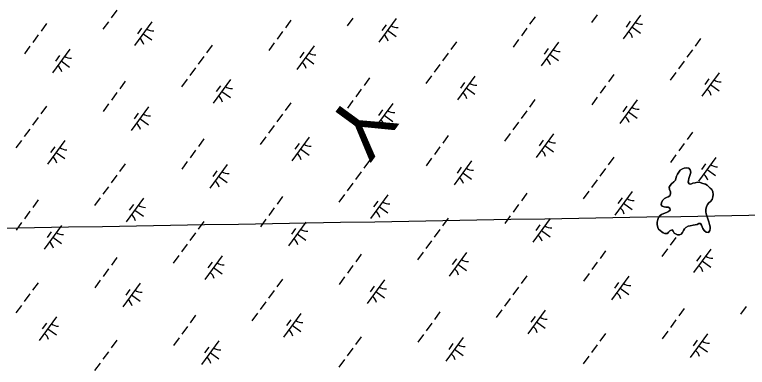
# Model space of a CAD drawing. Extents: x 3905714 to 3926767, y 183354 to 205755.
# Drawn here: x 3912599 to 3913848, y 193112 to 193713 of the extents above; entities that cross this region are included whole.
import ezdxf

# ---------------------------------------------------------------- set-up
doc = ezdxf.new("R2010")
doc.units = 0
for name, color, linetype in [('V-GRID-MAJR', 7, 'Continuous'), ('V-RIVR-IDEN', 7, 'Continuous'), ('V-TOPO-SHOR', 7, 'Continuous'), ('V-WETL-SWMP', 7, 'Continuous')]:
    doc.layers.add(name, color=color, linetype=linetype)

msp = doc.modelspace()

# ---------------------------------------------------------------- linework, layer by layer
at = {"layer": 'V-GRID-MAJR'}
msp.add_spline([(3911066.2, 193323.4), (3914779.2, 193387.5), (3920106, 193480.1), (3922587.2, 193523.5)], degree=3, dxfattribs=at)
at = {"layer": 'V-TOPO-SHOR'}
for points in [[(3913755.8, 193354.6), (3913751.1, 193353.4), (3913747.3, 193352.5), (3913743.7, 193350.7), (3913741.4, 193348.3), (3913739.7, 193345.3), (3913738, 193342), (3913735.7, 193339.4), (3913732.8, 193338), (3913729.5, 193338), (3913726, 193339.5), (3913723.4, 193341.1), (3913721.8, 193344), (3913719.9, 193346.3), (3913715.9, 193344.9), (3913714, 193342.3), (3913711.9, 193340), (3913707.9, 193340), (3913704.8, 193341.2), (3913702.3, 193342.9), (3913699.4, 193345.3), (3913697.1, 193347.6), (3913695.9, 193350.7), (3913694.8, 193355.6), (3913694.6, 193359.4), (3913695.6, 193364.1), (3913697, 193367.6), (3913699.4, 193370.7), (3913701.7, 193372.6), (3913705.7, 193374.4), (3913710.5, 193376), (3913714, 193377.7), (3913716.6, 193379.8), (3913716.2, 193383.5), (3913713.3, 193385.2), (3913709.6, 193385), (3913706.3, 193385.5), (3913703, 193386.7), (3913701.4, 193389.3), (3913701.8, 193393), (3913704.2, 193397.3), (3913707.1, 193399.8), (3913710.6, 193401.5), (3913713.4, 193402.6), (3913716, 193404.7), (3913717.5, 193407.8), (3913717.5, 193411.3), (3913715.6, 193415.1), (3913715.2, 193419.1), (3913716.6, 193422.2), (3913719.2, 193425), (3913723, 193428.2), (3913725.9, 193431.1), (3913726.6, 193434.1), (3913727.3, 193438.3), (3913729.2, 193441.6), (3913731.3, 193444.9), (3913733.5, 193448.2), (3913737.5, 193450.5), (3913740.8, 193451.7), (3913744.8, 193452.1), (3913748.3, 193451.9), (3913750.9, 193449), (3913751.8, 193444.6), (3913751.1, 193440.6), (3913749.7, 193437.3), (3913748.7, 193434), (3913747.8, 193430.9), (3913747.3, 193427.6), (3913749.1, 193424.8), (3913752.2, 193424.5), (3913755.5, 193425.9), (3913759.5, 193426.9), (3913763.5, 193427.8), (3913768, 193427), (3913772.2, 193425.8), (3913777.1, 193424.2), (3913780, 193422.5), (3913782.3, 193420.4), (3913784.9, 193417.8), (3913787.5, 193415.4), (3913789.6, 193411.4), (3913790.2, 193406.9), (3913789.5, 193402.7), (3913788.3, 193398.2), (3913785.5, 193394.9), (3913782.8, 193392.6), (3913780.2, 193389.8), (3913778.6, 193385.8), (3913777.4, 193382), (3913777.6, 193377.3), (3913778, 193374), (3913779.9, 193368.8), (3913780.8, 193365.3), (3913782.4, 193360.1), (3913783.8, 193355.6), (3913784.7, 193351.6), (3913784.7, 193348.5), (3913784.5, 193345.5), (3913782.3, 193342.2), (3913778.1, 193342.4)], [(3913778.1, 193342.4), (3913774.6, 193345.5), (3913772.5, 193348.8), (3913770.1, 193354.5), (3913768.7, 193357.3), (3913765.7, 193357.1), (3913762.6, 193355.7), (3913755.8, 193354.6)]]:
    msp.add_lwpolyline(points, dxfattribs=at)
at = {"layer": 'V-WETL-SWMP'}
for p, q in [((3912772.8, 193720.9), (3912763.4, 193708)), ((3913175.3, 193707.3), (3913165.9, 193694.4)), ((3913249.5, 193707), (3913220, 193666.7)), ((3913486.6, 193709.9), (3913477.1, 193697)), ((3913592, 193713.2), (3913582.6, 193700.3)), ((3913666.2, 193712.8), (3913636.6, 193672.5)), ((3912653.2, 193698.2), (3912643.8, 193685.3)), ((3912758.7, 193701.5), (3912749.2, 193688.6)), ((3912832.8, 193701.2), (3912803.3, 193660.9)), ((3913069.9, 193704), (3913060.5, 193691.1)), ((3913232.1, 193696.2), (3913225, 193686.6)), ((3913648.7, 193702.1), (3913641.6, 193692.4)), ((3913651.4, 193692.7), (3913665.9, 193682)), ((3912815.4, 193690.4), (3912808.3, 193680.7)), ((3912818.1, 193681), (3912832.6, 193670.4)), ((3913055.7, 193684.7), (3913046.3, 193671.8)), ((3913234.7, 193686.8), (3913249.3, 193676.2)), ((3913472.4, 193690.5), (3913463, 193677.6)), ((3912639.1, 193678.9), (3912629.6, 193666)), ((3913352.1, 193667.1), (3913342.6, 193654.2)), ((3913458.2, 193671.2), (3913448.8, 193658.2)), ((3913768.7, 193672.9), (3913759.3, 193660)), ((3912624.9, 193659.5), (3912615.4, 193646.6)), ((3912692.9, 193654.7), (3912663.3, 193614.3)), ((3912935.4, 193661.3), (3912925.9, 193648.4)), ((3913041.6, 193665.3), (3913032.1, 193652.4)), ((3913109.6, 193660.5), (3913080, 193620.2)), ((3913526.2, 193666.3), (3913496.7, 193626)), ((3913508.8, 193655.6), (3913501.7, 193645.9)), ((3912675.4, 193643.9), (3912668.3, 193634.2)), ((3913092.1, 193649.7), (3913085, 193640)), ((3913337.9, 193647.8), (3913328.4, 193634.8)), ((3913511.5, 193646.2), (3913526, 193635.5)), ((3913754.6, 193653.6), (3913745.1, 193640.7)), ((3912678.1, 193634.5), (3912692.6, 193623.9)), ((3912921.2, 193641.9), (3912911.8, 193629)), ((3913094.8, 193640.3), (3913109.3, 193629.7)), ((3913740.4, 193634.2), (3913730.9, 193621.3)), ((3912907, 193622.6), (3912897.6, 193609.7)), ((3913323.7, 193628.4), (3913314.2, 193615.5)), ((3913204.1, 193605.7), (3913194.6, 193592.8)), ((3913309.5, 193609), (3913300.1, 193596.1)), ((3913383.7, 193608.7), (3913354.1, 193568.4)), ((3913620.8, 193611.6), (3913611.3, 193598.7)), ((3913726.2, 193614.9), (3913716.7, 193601.9)), ((3913800.4, 193614.5), (3913770.8, 193574.2)), ((3912787.4, 193599.9), (3912778, 193587)), ((3912892.8, 193603.2), (3912883.4, 193590.3)), ((3912967, 193602.9), (3912937.5, 193562.5)), ((3912949.6, 193592.1), (3912942.5, 193582.4)), ((3913366.2, 193597.9), (3913359.2, 193588.3)), ((3913606.6, 193592.2), (3913597.1, 193579.3)), ((3913782.9, 193603.8), (3913775.8, 193594.1)), ((3913785.6, 193594.4), (3913800.1, 193583.7)), ((3912773.2, 193580.6), (3912763.8, 193567.6)), ((3912952.2, 193582.7), (3912966.8, 193572.1)), ((3913189.9, 193586.4), (3913180.5, 193573.5)), ((3913368.9, 193588.5), (3913383.4, 193577.9)), ((3913175.7, 193567), (3913166.3, 193554.1)), ((3913486.2, 193568.8), (3913476.8, 193555.9)), ((3913592.4, 193572.8), (3913583, 193559.9)), ((3913660.4, 193568), (3913630.9, 193527.7)), ((3912652.9, 193557.2), (3912643.4, 193544.2)), ((3912759.1, 193561.2), (3912749.6, 193548.3)), ((3912827.1, 193556.4), (3912797.5, 193516)), ((3913069.6, 193563), (3913060.1, 193550.1)), ((3913243.7, 193562.2), (3913214.2, 193521.9)), ((3913643, 193557.2), (3913635.9, 193547.6)), ((3912809.6, 193545.6), (3912802.5, 193535.9)), ((3913055.4, 193543.6), (3913045.9, 193530.7)), ((3913226.3, 193551.4), (3913219.2, 193541.7)), ((3913229, 193542), (3913243.5, 193531.4)), ((3913472.1, 193549.4), (3913462.6, 193536.5)), ((3913645.6, 193547.8), (3913660.2, 193537.2)), ((3912638.7, 193537.8), (3912629.3, 193524.9)), ((3912812.3, 193536.2), (3912826.8, 193525.6)), ((3913457.9, 193530.1), (3913448.4, 193517.2)), ((3912624.5, 193518.4), (3912615.1, 193505.5)), ((3913041.2, 193524.3), (3913031.7, 193511.4)), ((3913027, 193504.9), (3913017.6, 193492)), ((3913101.2, 193504.6), (3913071.7, 193464.2)), ((3913338.3, 193507.4), (3913328.8, 193494.5)), ((3913443.7, 193510.7), (3913434.2, 193497.8)), ((3913517.9, 193510.4), (3913488.3, 193470.1)), ((3913755, 193513.3), (3913745.5, 193500.4)), ((3912610.3, 193499.1), (3912600.9, 193486.2)), ((3912684.5, 193498.7), (3912655, 193458.4)), ((3912921.6, 193501.6), (3912912.2, 193488.7)), ((3913083.8, 193493.8), (3913076.7, 193484.1)), ((3913500.4, 193499.6), (3913493.3, 193490)), ((3913740.8, 193493.9), (3913731.3, 193481)), ((3912667.1, 193488), (3912660, 193478.3)), ((3912907.4, 193482.2), (3912898, 193469.3)), ((3913086.4, 193484.4), (3913100.9, 193473.8)), ((3913324.1, 193488.1), (3913314.6, 193475.2)), ((3913503.1, 193490.2), (3913517.6, 193479.6)), ((3912669.8, 193478.6), (3912684.3, 193467.9)), ((3913309.9, 193468.7), (3913300.5, 193455.8)), ((3913620.4, 193470.5), (3913611, 193457.6)), ((3913726.6, 193474.5), (3913717.1, 193461.6)), ((3913794.6, 193469.7), (3913765, 193429.4)), ((3912787.1, 193458.8), (3912777.6, 193445.9)), ((3912893.2, 193462.9), (3912883.8, 193450)), ((3912961.2, 193458.1), (3912931.7, 193417.7)), ((3913203.8, 193464.7), (3913194.3, 193451.8)), ((3913377.9, 193463.9), (3913348.4, 193423.5)), ((3913777.1, 193458.9), (3913770, 193449.3)), ((3912943.8, 193447.3), (3912936.7, 193437.6)), ((3913189.6, 193445.3), (3913180.1, 193432.4)), ((3913360.5, 193453.1), (3913353.4, 193443.4)), ((3913363.1, 193443.7), (3913377.7, 193433.1)), ((3913606.2, 193451.1), (3913596.8, 193438.2)), ((3913731.3, 193444.9), (3913729.2, 193441.6)), ((3913733.5, 193448.2), (3913731.3, 193444.9)), ((3913737.5, 193450.5), (3913733.5, 193448.2)), ((3913740.8, 193451.7), (3913737.5, 193450.5)), ((3913744.8, 193452.1), (3913740.8, 193451.7)), ((3913748.3, 193451.9), (3913744.8, 193452.1)), ((3913750.9, 193449), (3913748.3, 193451.9)), ((3913751.8, 193444.6), (3913750.9, 193449)), ((3913751.1, 193440.6), (3913751.8, 193444.6)), ((3913779.8, 193449.5), (3913794.3, 193438.9)), ((3912772.9, 193439.5), (3912763.4, 193426.6)), ((3912946.5, 193437.9), (3912961, 193427.3)), ((3913592.1, 193431.8), (3913582.6, 193418.9)), ((3913725.9, 193431.1), (3913723, 193428.2)), ((3913726.6, 193434.1), (3913725.9, 193431.1)), ((3913727.3, 193438.3), (3913726.6, 193434.1)), ((3913729.2, 193441.6), (3913727.3, 193438.3)), ((3913747.3, 193427.6), (3913747.8, 193430.9)), ((3913747.8, 193430.9), (3913748.7, 193434)), ((3913748.7, 193434), (3913749.7, 193437.3)), ((3913749.7, 193437.3), (3913751.1, 193440.6)), ((3912758.7, 193420.1), (3912749.3, 193407.2)), ((3913175.4, 193426), (3913165.9, 193413)), ((3913716.6, 193422.2), (3913715.2, 193419.1)), ((3913715.2, 193419.1), (3913715.6, 193415.1)), ((3913719.2, 193425), (3913716.6, 193422.2)), ((3913723, 193428.2), (3913719.2, 193425)), ((3913749.1, 193424.8), (3913747.3, 193427.6)), ((3913752.2, 193424.5), (3913749.1, 193424.8)), ((3913755.5, 193425.9), (3913752.2, 193424.5)), ((3913759.5, 193426.9), (3913755.5, 193425.9)), ((3913763.5, 193427.8), (3913759.5, 193426.9)), ((3913768, 193427), (3913763.5, 193427.8)), ((3913772.2, 193425.8), (3913768, 193427)), ((3913777.1, 193424.2), (3913772.2, 193425.8)), ((3913780, 193422.5), (3913777.1, 193424.2)), ((3913782.3, 193420.4), (3913780, 193422.5)), ((3913784.9, 193417.8), (3913782.3, 193420.4)), ((3913787.5, 193415.4), (3913784.9, 193417.8)), ((3913161.2, 193406.6), (3913151.7, 193393.7)), ((3913235.4, 193406.3), (3913205.8, 193365.9)), ((3913472.5, 193409.1), (3913463, 193396.2)), ((3913577.9, 193412.4), (3913568.4, 193399.5)), ((3913652.1, 193412.1), (3913622.5, 193371.8)), ((3913716, 193404.7), (3913713.4, 193402.6)), ((3913715.6, 193415.1), (3913717.5, 193411.3)), ((3913717.5, 193407.8), (3913716, 193404.7)), ((3913717.5, 193411.3), (3913717.5, 193407.8)), ((3913789.6, 193411.4), (3913787.5, 193415.4)), ((3913789.5, 193402.7), (3913790.2, 193406.9)), ((3913790.2, 193406.9), (3913789.6, 193411.4)), ((3912639.1, 193397.5), (3912629.7, 193384.6)), ((3912744.5, 193400.8), (3912735.1, 193387.9)), ((3912818.7, 193400.4), (3912789.2, 193360.1)), ((3913055.8, 193403.3), (3913046.3, 193390.4)), ((3913217.9, 193395.5), (3913210.8, 193385.8)), ((3913634.6, 193401.3), (3913627.5, 193391.6)), ((3913701.8, 193393), (3913701.4, 193389.3)), ((3913704.2, 193397.3), (3913701.8, 193393)), ((3913707.1, 193399.8), (3913704.2, 193397.3)), ((3913710.6, 193401.5), (3913707.1, 193399.8)), ((3913713.4, 193402.6), (3913710.6, 193401.5)), ((3913780.2, 193389.8), (3913782.8, 193392.6)), ((3913782.8, 193392.6), (3913785.5, 193394.9)), ((3913785.5, 193394.9), (3913788.3, 193398.2)), ((3913788.3, 193398.2), (3913789.5, 193402.7)), ((3912801.3, 193389.7), (3912794.2, 193380)), ((3912803.9, 193380.3), (3912818.5, 193369.6)), ((3913041.6, 193383.9), (3913032.1, 193371)), ((3913220.6, 193386.1), (3913235.1, 193375.5)), ((3913458.3, 193389.8), (3913448.8, 193376.9)), ((3913637.3, 193391.9), (3913651.8, 193381.3)), ((3913701.4, 193389.3), (3913703, 193386.7)), ((3913703, 193386.7), (3913706.3, 193385.5)), ((3913706.3, 193385.5), (3913709.6, 193385)), ((3913709.6, 193385), (3913713.3, 193385.2)), ((3913713.3, 193385.2), (3913716.2, 193383.5)), ((3913716.6, 193379.8), (3913714, 193377.7)), ((3913716.2, 193383.5), (3913716.6, 193379.8)), ((3913777.4, 193382), (3913778.6, 193385.8)), ((3913777.6, 193377.3), (3913777.4, 193382)), ((3913778.6, 193385.8), (3913780.2, 193389.8)), ((3912624.9, 193378.1), (3912615.5, 193365.2)), ((3913444.1, 193370.4), (3913434.6, 193357.5)), ((3913697, 193367.6), (3913695.6, 193364.1)), ((3913699.4, 193370.7), (3913697, 193367.6)), ((3913701.7, 193372.6), (3913699.4, 193370.7)), ((3913705.7, 193374.4), (3913701.7, 193372.6)), ((3913710.5, 193376), (3913705.7, 193374.4)), ((3913714, 193377.7), (3913710.5, 193376)), ((3913778, 193374), (3913777.6, 193377.3)), ((3913779.9, 193368.8), (3913778, 193374)), ((3913780.8, 193365.3), (3913779.9, 193368.8)), ((3912610.7, 193358.8), (3912601.3, 193345.9)), ((3912921.3, 193360.5), (3912911.8, 193347.6)), ((3913027.4, 193364.6), (3913018, 193351.7)), ((3913095.4, 193359.8), (3913065.9, 193319.4)), ((3913337.9, 193366.4), (3913328.5, 193353.5)), ((3913512.1, 193365.6), (3913482.6, 193325.2)), ((3913494.6, 193354.8), (3913487.6, 193345.1)), ((3913695.6, 193364.1), (3913694.6, 193359.4)), ((3913694.6, 193359.4), (3913694.8, 193355.6)), ((3913694.8, 193355.6), (3913695.9, 193350.7)), ((3913751.1, 193353.4), (3913755.8, 193354.6)), ((3913755.8, 193354.6), (3913762.6, 193355.7)), ((3913762.6, 193355.7), (3913765.7, 193357.1)), ((3913765.7, 193357.1), (3913768.7, 193357.3)), ((3913768.7, 193357.3), (3913770.1, 193354.5)), ((3913782.4, 193360.1), (3913780.8, 193365.3)), ((3913783.8, 193355.6), (3913782.4, 193360.1)), ((3913784.7, 193351.6), (3913783.8, 193355.6)), ((3912678.8, 193353.9), (3912649.2, 193313.6)), ((3912661.3, 193343.2), (3912654.2, 193333.5)), ((3913078, 193349), (3913070.9, 193339.3)), ((3913323.7, 193347), (3913314.3, 193334.1)), ((3913497.3, 193345.4), (3913511.8, 193334.8)), ((3913695.9, 193350.7), (3913697.1, 193347.6)), ((3913697.1, 193347.6), (3913699.4, 193345.3)), ((3913699.4, 193345.3), (3913702.3, 193342.9)), ((3913702.3, 193342.9), (3913704.8, 193341.2)), ((3913711.9, 193340), (3913714, 193342.3)), ((3913714, 193342.3), (3913715.9, 193344.9)), ((3913715.9, 193344.9), (3913719.9, 193346.3)), ((3913719.9, 193346.3), (3913721.8, 193344)), ((3913721.8, 193344), (3913723.4, 193341.1)), ((3913738, 193342), (3913739.7, 193345.3)), ((3913739.7, 193345.3), (3913741.4, 193348.3)), ((3913741.4, 193348.3), (3913743.7, 193350.7)), ((3913743.7, 193350.7), (3913747.3, 193352.5)), ((3913747.3, 193352.5), (3913751.1, 193353.4)), ((3913770.1, 193354.5), (3913772.5, 193348.8)), ((3913772.5, 193348.8), (3913774.6, 193345.5)), ((3913774.6, 193345.5), (3913778.1, 193342.4)), ((3913778.1, 193342.4), (3913782.3, 193342.2)), ((3913782.3, 193342.2), (3913784.5, 193345.5)), ((3913784.5, 193345.5), (3913784.7, 193348.5)), ((3913784.7, 193348.5), (3913784.7, 193351.6)), ((3912664, 193333.8), (3912678.5, 193323.1)), ((3912907.1, 193341.2), (3912897.6, 193328.3)), ((3913080.7, 193339.6), (3913095.2, 193328.9)), ((3913704.8, 193341.2), (3913707.9, 193340)), ((3913707.9, 193340), (3913711.9, 193340)), ((3913726.2, 193333.5), (3913716.8, 193320.6)), ((3913723.4, 193341.1), (3913726, 193339.5)), ((3913726, 193339.5), (3913729.5, 193338)), ((3913729.5, 193338), (3913732.8, 193338)), ((3913732.8, 193338), (3913735.7, 193339.4)), ((3913735.7, 193339.4), (3913738, 193342)), ((3912892.9, 193321.8), (3912883.4, 193308.9)), ((3913309.6, 193327.6), (3913300.1, 193314.7)), ((3913190, 193305), (3913180.5, 193292.1)), ((3913295.4, 193308.3), (3913285.9, 193295.4)), ((3913369.6, 193308), (3913340, 193267.6)), ((3913606.6, 193310.8), (3913597.2, 193297.9)), ((3913712.1, 193314.1), (3913702.6, 193301.2)), ((3913786.2, 193313.8), (3913756.7, 193273.5)), ((3912773.3, 193299.2), (3912763.8, 193286.3)), ((3912878.7, 193302.5), (3912869.2, 193289.6)), ((3912952.9, 193302.1), (3912923.3, 193261.8)), ((3913352.1, 193297.2), (3913345, 193287.5)), ((3913768.8, 193303), (3913761.7, 193293.3)), ((3913771.5, 193293.6), (3913786, 193283)), ((3912759.1, 193279.8), (3912749.7, 193266.9)), ((3912935.4, 193291.4), (3912928.3, 193281.7)), ((3912938.1, 193282), (3912952.6, 193271.3)), ((3913175.8, 193285.6), (3913166.3, 193272.7)), ((3913354.8, 193287.8), (3913369.3, 193277.2)), ((3913592.5, 193291.5), (3913583, 193278.6)), ((3913472.1, 193268.1), (3913462.7, 193255.2)), ((3913578.3, 193272.1), (3913568.8, 193259.2)), ((3913646.3, 193267.3), (3913616.7, 193226.9)), ((3912638.8, 193256.4), (3912629.3, 193243.5)), ((3912744.9, 193260.5), (3912735.5, 193247.5)), ((3912812.9, 193255.6), (3912783.4, 193215.3)), ((3913055.4, 193262.2), (3913046, 193249.3)), ((3913161.6, 193266.3), (3913152.1, 193253.4)), ((3913229.6, 193261.4), (3913200.1, 193221.1)), ((3913628.8, 193256.5), (3913621.7, 193246.8)), ((3912795.5, 193244.9), (3912788.4, 193235.2)), ((3913041.3, 193242.9), (3913031.8, 193230)), ((3913212.2, 193250.7), (3913205.1, 193241)), ((3913457.9, 193248.7), (3913448.5, 193235.8)), ((3913631.5, 193247.1), (3913646, 193236.5)), ((3912624.6, 193237.1), (3912615.1, 193224.1)), ((3912798.2, 193235.5), (3912812.7, 193224.8)), ((3913214.8, 193241.3), (3913229.4, 193230.6)), ((3912610.4, 193217.7), (3912600.9, 193204.8)), ((3913027.1, 193223.5), (3913017.6, 193210.6)), ((3913443.7, 193229.3), (3913434.3, 193216.4)), ((3913324.1, 193206.7), (3913314.7, 193193.8)), ((3913429.6, 193210), (3913420.1, 193197.1)), ((3913503.7, 193209.7), (3913474.2, 193169.3)), ((3913740.8, 193212.5), (3913731.4, 193199.6)), ((3913846.2, 193215.8), (3913836.8, 193202.9)), ((3912670.4, 193198), (3912640.8, 193157.7)), ((3912907.5, 193200.9), (3912898, 193188)), ((3913012.9, 193204.2), (3913003.4, 193191.3)), ((3913087.1, 193203.8), (3913057.5, 193163.5)), ((3913069.6, 193193.1), (3913062.5, 193183.4)), ((3913486.3, 193198.9), (3913479.2, 193189.2)), ((3913726.6, 193193.2), (3913717.2, 193180.2)), ((3912652.9, 193187.2), (3912645.8, 193177.6)), ((3912893.3, 193181.5), (3912883.8, 193168.6)), ((3913072.3, 193183.7), (3913086.8, 193173)), ((3913310, 193187.3), (3913300.5, 193174.4)), ((3913489, 193189.5), (3913503.5, 193178.8)), ((3912655.6, 193177.8), (3912670.1, 193167.2)), ((3913295.8, 193168), (3913286.3, 193155.1)), ((3913606.3, 193169.8), (3913596.8, 193156.9)), ((3913712.5, 193173.8), (3913703, 193160.9)), ((3913780.5, 193169), (3913750.9, 193128.6)), ((3912772.9, 193158.1), (3912763.5, 193145.2)), ((3912879.1, 193162.1), (3912869.6, 193149.2)), ((3912947.1, 193157.3), (3912917.6, 193117)), ((3913189.6, 193163.9), (3913180.2, 193151)), ((3913363.8, 193163.1), (3913334.2, 193122.8)), ((3913763, 193158.2), (3913755.9, 193148.5)), ((3912929.7, 193146.5), (3912922.6, 193136.9)), ((3913175.4, 193144.6), (3913166, 193131.7)), ((3913346.3, 193152.4), (3913339.2, 193142.7)), ((3913349, 193143), (3913363.5, 193132.3)), ((3913592.1, 193150.4), (3913582.6, 193137.5)), ((3913765.7, 193148.8), (3913780.2, 193138.2)), ((3912758.8, 193138.7), (3912749.3, 193125.8)), ((3912932.3, 193137.1), (3912946.9, 193126.5)), ((3913577.9, 193131), (3913568.5, 193118.1)), ((3912744.6, 193119.4), (3912735.1, 193106.5)), ((3913161.2, 193125.2), (3913151.8, 193112.3))]:
    msp.add_line(p, q, dxfattribs=at)
for centre, start, end in [((3913251.3, 193709), 233, 274.5436), ((3913667.9, 193714.8), 233, 274.5436), ((3912834.6, 193703.2), 233, 274.5436), ((3913635.3, 193670.2), 13, 54.5436), ((3912801.9, 193658.6), 13, 54.5436), ((3913218.6, 193664.4), 13, 54.5436), ((3912694.6, 193656.6), 233, 274.5436), ((3913111.3, 193662.5), 233, 274.5436), ((3913528, 193668.3), 233, 274.5436), ((3913078.7, 193617.9), 13, 54.5436), ((3913495.3, 193623.7), 13, 54.5436), ((3912662, 193612.1), 13, 54.5436), ((3913385.4, 193610.7), 233, 274.5436), ((3913802.1, 193616.5), 233, 274.5436), ((3912968.8, 193604.9), 233, 274.5436), ((3913352.8, 193566.1), 13, 54.5436), ((3913769.5, 193571.9), 13, 54.5436), ((3912936.1, 193560.3), 13, 54.5436), ((3913662.2, 193570), 233, 274.5436), ((3912828.8, 193558.3), 233, 274.5436), ((3913245.5, 193564.2), 233, 274.5436), ((3913212.8, 193519.6), 13, 54.5436), ((3913629.5, 193525.4), 13, 54.5436), ((3912796.2, 193513.8), 13, 54.5436), ((3913102.9, 193506.5), 233, 274.5436), ((3913519.6, 193512.4), 233, 274.5436), ((3912686.3, 193500.7), 233, 274.5436), ((3913487, 193467.8), 13, 54.5436), ((3912653.6, 193456.2), 13, 54.5436), ((3913070.3, 193462), 13, 54.5436), ((3913796.3, 193471.7), 233, 274.5436), ((3912963, 193460), 233, 274.5436), ((3913379.7, 193465.9), 233, 274.5436), ((3912930.3, 193415.5), 13, 54.5436), ((3913347, 193421.3), 13, 54.5436), ((3913763.7, 193427.1), 13, 54.5436), ((3913237.1, 193408.2), 233, 274.5436), ((3913653.8, 193414.1), 233, 274.5436), ((3912820.4, 193402.4), 233, 274.5436), ((3913621.1, 193369.5), 13, 54.5436), ((3912787.8, 193357.9), 13, 54.5436), ((3913204.5, 193363.7), 13, 54.5436), ((3913097.2, 193361.7), 233, 274.5436), ((3913513.8, 193367.6), 233, 274.5436), ((3912680.5, 193355.9), 233, 274.5436), ((3913064.5, 193317.2), 13, 54.5436), ((3913481.2, 193323), 13, 54.5436), ((3912647.8, 193311.3), 13, 54.5436), ((3913371.3, 193309.9), 233, 274.5436), ((3913788, 193315.8), 233, 274.5436), ((3912954.6, 193304.1), 233, 274.5436), ((3913338.7, 193265.4), 13, 54.5436), ((3913755.3, 193271.2), 13, 54.5436), ((3912922, 193259.5), 13, 54.5436), ((3913648, 193269.2), 233, 274.5436), ((3912814.7, 193257.6), 233, 274.5436), ((3913231.3, 193263.4), 233, 274.5436), ((3913198.7, 193218.9), 13, 54.5436), ((3913615.4, 193224.7), 13, 54.5436), ((3912782, 193213), 13, 54.5436), ((3913505.5, 193211.6), 233, 274.5436), ((3912672.1, 193200), 233, 274.5436), ((3913088.8, 193205.8), 233, 274.5436), ((3913472.8, 193167.1), 13, 54.5436), ((3912639.5, 193155.4), 13, 54.5436), ((3913056.2, 193161.2), 13, 54.5436), ((3913782.2, 193170.9), 233, 274.5436), ((3912948.9, 193159.3), 233, 274.5436), ((3913365.5, 193165.1), 233, 274.5436), ((3913332.9, 193120.6), 13, 54.5436), ((3913749.6, 193126.4), 13, 54.5436), ((3912916.2, 193114.7), 13, 54.5436)]:
    msp.add_arc(centre, 17.6, start, end, dxfattribs=at)

# ---------------------------------------------------------------- texts
at = {"layer": 'V-RIVR-IDEN'}
msp.add_text('Y', height=100, rotation=233.8714, dxfattribs=at).set_placement((3913175.9, 193588.9))

doc.saveas('drawing.dxf')
